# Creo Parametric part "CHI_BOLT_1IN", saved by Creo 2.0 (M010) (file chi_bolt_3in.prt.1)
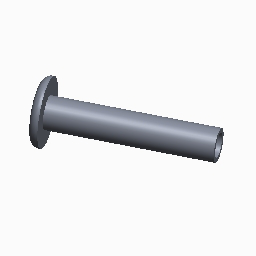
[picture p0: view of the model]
Units: Inch lbm Second (Pro/E Default); INCH, POUND, SECS

Created from: INLBS_PART_SOLID.PRT

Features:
  1. datum plane "RIGHT"
  2. datum plane "TOP"
  3. datum plane "FRONT"
  4. coordinate system
  5. sketch "Sketch 1"
  6. extrusion "Extrude 1", "Sketch 1"
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
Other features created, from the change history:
  sketch "Sketch 2"
  extrusion "Extrude 2"
  round "Round 1"

Surfaces: 6 plane, 6 cylinder, 2 torus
